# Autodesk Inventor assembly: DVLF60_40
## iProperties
Created: 2010-03
Part Number: DVLF60_40
Document SubType Name: Assembly
Designer: TB
Mass: 1110.19 g
Surface Area: 1885.6 cm^2
Volume: 1110.19 cm^3
Density: 1 g/cm^3
Description: KM DVLF 60/40 - 100 mm
Slaglengde: 100.000 mm
Author: TB
